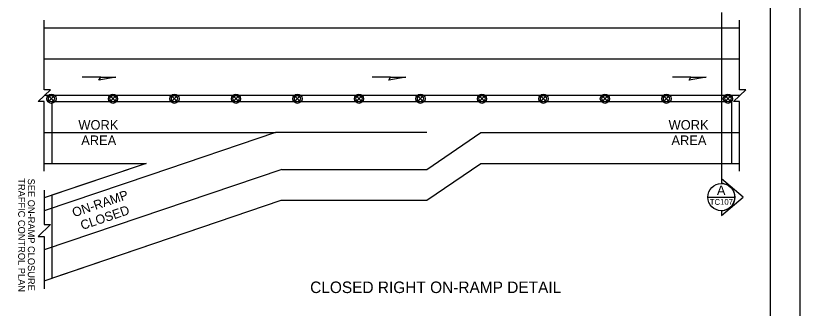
# Model space of a CAD drawing. Extents: x 99999 to 100116, y 99995 to 100013.
# Drawn here: x 100067.9 to 100076.06, y 100001.64 to 100004.69 of the extents above; entities that cross this region are included whole.
import ezdxf

# ---------------------------------------------------------------- set-up
doc = ezdxf.new("R2010")
doc.units = 0
for name, color, linetype in [('RD_MK_LineEdgeYellow', 7, 'Continuous'), ('RD_MK_LineLane', 7, 'Continuous'), ('SH_DE_DetailHeading2Text', 7, 'Continuous'), ('SH_GI_PlotLimits', 7, 'Continuous'), ('SH_GI_SheetBorder', 7, 'Continuous'), ('SH_TI_WZSectionCut', 7, 'Continuous'), ('TR_WZ_TrafficSafetyDrum', 7, 'Continuous'), ('TR_WZ_WorkAreaLabel', 7, 'Continuous'), ('TR_WZ_WorkZoneDetails', 7, 'Continuous')]:
    doc.layers.add(name, color=color, linetype=linetype)

msp = doc.modelspace()

# ---------------------------------------------------------------- linework, layer by layer
at = {"layer": 'RD_MK_LineEdgeYellow'}
for p, q in [((100068.195, 100004.238), (100075.43, 100004.238)), ((100068.195, 100003.47), (100069.2533, 100003.47)), ((100072.1758, 100003.086), (100072.7368, 100003.47)), ((100072.7368, 100003.47), (100075.43, 100003.47)), ((100070.6655, 100003.086), (100068.195, 100002.2517)), ((100070.6655, 100003.086), (100072.1758, 100003.086)), ((100069.2943, 100003.0282), (100068.195, 100002.657))]:
    msp.add_line(p, q, dxfattribs=at)
at = {"layer": 'RD_MK_LineLane'}
for points in [[(100075.43, 100003.854), (100068.195, 100003.854)], [(100072.1758, 100003.47), (100070.6024, 100003.47)]]:
    msp.add_lwpolyline(points, dxfattribs=at)
at = {"layer": 'SH_GI_PlotLimits'}
msp.add_lwpolyline([(100059.0625, 99999.6875), (100076.0625, 99999.6875), (100076.0625, 100010.6875), (100059.0625, 100010.6875)], close=True, dxfattribs=at)
at = {"layer": 'SH_GI_SheetBorder'}
msp.add_line((100075.75, 100010.375), (100075.75, 100000), dxfattribs=at)
at = {"layer": 'SH_TI_WZSectionCut'}
for p, q in [((100075.2407, 100004.718), (100075.2407, 100002.99)), ((100075.2407, 100002.99), (100075.2407, 100002.94)), ((100075.4689, 100002.7988), (100075.2407, 100002.99)), ((100075.2407, 100002.6077), (100075.4689, 100002.7988)), ((100075.2407, 100002.6576), (100075.2407, 100002.6077))]:
    msp.add_line(p, q, dxfattribs=at)
msp.add_lwpolyline([(100075.0995, 100002.7988), (100075.3819, 100002.7988)], dxfattribs=at)
msp.add_circle((100075.2407, 100002.7988), 0.1412, dxfattribs=at)
msp.add_arc((100075.2407, 100002.7988), 0.1412, 269.99779, 90.00221, dxfattribs=at)
at = {"layer": 'TR_WZ_TrafficSafetyDrum'}
for p, q in [((100068.2468, 100003.8446), (100068.292, 100003.7993)), ((100068.292, 100003.8446), (100068.2468, 100003.7993)), ((100068.8868, 100003.8446), (100068.932, 100003.7993)), ((100068.932, 100003.8446), (100068.8868, 100003.7993)), ((100069.5268, 100003.8446), (100069.572, 100003.7993)), ((100069.572, 100003.8446), (100069.5268, 100003.7993)), ((100070.1668, 100003.8446), (100070.212, 100003.7993)), ((100070.212, 100003.8446), (100070.1668, 100003.7993)), ((100070.8068, 100003.8446), (100070.852, 100003.7993)), ((100070.852, 100003.8446), (100070.8068, 100003.7993)), ((100071.4468, 100003.8446), (100071.492, 100003.7993)), ((100071.492, 100003.8446), (100071.4468, 100003.7993)), ((100072.0868, 100003.8446), (100072.132, 100003.7993)), ((100072.132, 100003.8446), (100072.0868, 100003.7993)), ((100072.7268, 100003.8446), (100072.772, 100003.7993)), ((100072.772, 100003.8446), (100072.7268, 100003.7993)), ((100073.3668, 100003.8446), (100073.412, 100003.7993)), ((100073.412, 100003.8446), (100073.3668, 100003.7993)), ((100074.0068, 100003.8446), (100074.052, 100003.7993)), ((100074.052, 100003.8446), (100074.0068, 100003.7993)), ((100074.6468, 100003.8446), (100074.692, 100003.7993)), ((100074.692, 100003.8446), (100074.6468, 100003.7993)), ((100075.2868, 100003.8446), (100075.332, 100003.7993)), ((100075.332, 100003.8446), (100075.2868, 100003.7993))]:
    msp.add_line(p, q, dxfattribs=at)
for centre, radius in [((100068.2694, 100003.822), 0.048), ((100068.2694, 100003.822), 0.048), ((100068.2694, 100003.822), 0.032), ((100068.9094, 100003.822), 0.048), ((100068.9094, 100003.822), 0.048), ((100068.9094, 100003.822), 0.032), ((100069.5494, 100003.822), 0.048), ((100069.5494, 100003.822), 0.048), ((100069.5494, 100003.822), 0.032), ((100070.1894, 100003.822), 0.048), ((100070.1894, 100003.822), 0.048), ((100070.1894, 100003.822), 0.032), ((100070.8294, 100003.822), 0.048), ((100070.8294, 100003.822), 0.048), ((100070.8294, 100003.822), 0.032), ((100071.4694, 100003.822), 0.048), ((100071.4694, 100003.822), 0.048), ((100071.4694, 100003.822), 0.032), ((100072.1094, 100003.822), 0.048), ((100072.1094, 100003.822), 0.048), ((100072.1094, 100003.822), 0.032), ((100072.7494, 100003.822), 0.048), ((100072.7494, 100003.822), 0.048), ((100072.7494, 100003.822), 0.032), ((100073.3894, 100003.822), 0.048), ((100073.3894, 100003.822), 0.048), ((100073.3894, 100003.822), 0.032), ((100074.0294, 100003.822), 0.048), ((100074.0294, 100003.822), 0.048), ((100074.0294, 100003.822), 0.032), ((100074.6694, 100003.822), 0.048), ((100074.6694, 100003.822), 0.048), ((100074.6694, 100003.822), 0.032), ((100075.3094, 100003.822), 0.048), ((100075.3094, 100003.822), 0.048), ((100075.3094, 100003.822), 0.032)]:
    msp.add_circle(centre, radius, dxfattribs=at)
at = {"layer": 'TR_WZ_WorkZoneDetails'}
for p, q in [((100068.195, 100004.558), (100075.43, 100004.558)), ((100068.782, 100004.046), (100068.5891, 100004.046)), ((100071.7994, 100004.046), (100071.6065, 100004.046)), ((100074.9242, 100004.046), (100074.7313, 100004.046)), ((100069.2533, 100003.47), (100070.6024, 100003.47)), ((100070.6024, 100003.47), (100069.2943, 100003.0282)), ((100068.195, 100003.15), (100069.2533, 100003.15)), ((100069.2533, 100003.15), (100068.195, 100002.7929)), ((100072.1758, 100002.766), (100072.7368, 100003.15)), ((100072.7368, 100003.15), (100075.43, 100003.15)), ((100068.195, 100001.928), (100070.6601, 100002.766)), ((100070.6601, 100002.766), (100072.1758, 100002.766))]:
    msp.add_line(p, q, dxfattribs=at)
for points in [[(100068.195, 100003.07), (100068.195, 100003.792), (100068.131, 100003.792), (100068.259, 100003.9159), (100068.195, 100003.9159), (100068.195, 100004.638)], [(100075.43, 100003.07), (100075.43, 100003.792), (100075.366, 100003.792), (100075.494, 100003.9159), (100075.43, 100003.9159), (100075.43, 100004.638)], [(100068.195, 100002.8701), (100068.195, 100002.5136), (100068.259, 100002.5136), (100068.131, 100002.3897), (100068.195, 100002.3897), (100068.195, 100001.8453)]]:
    msp.add_lwpolyline(points, dxfattribs=at)
for points in [[(100068.9392, 100004.046), (100068.7641, 100004.0151), (100068.782, 100004.046)], [(100071.9566, 100004.046), (100071.7815, 100004.0151), (100071.7994, 100004.046)], [(100075.0815, 100004.046), (100074.9064, 100004.0151), (100074.9242, 100004.046)], [(100068.275, 100003.79), (100068.275, 100003.15), (100069.2533, 100003.15), (100068.275, 100002.8199), (100068.275, 100002.8199), (100068.275, 100002.8199), (100068.275, 100001.9552), (100068.275, 100001.9552), (100068.275, 100001.9552), (100069.3341, 100002.3152), (100070.6601, 100002.766), (100072.1758, 100002.766), (100072.7368, 100003.15), (100075.35, 100003.15), (100075.35, 100003.79)]]:
    msp.add_lwpolyline(points, close=True, dxfattribs=at)

# ---------------------------------------------------------------- texts
at = {"layer": 'SH_DE_DetailHeading2Text'}
msp.add_text('CLOSED RIGHT ON-RAMP DETAIL', height=0.12, rotation=360, dxfattribs=at).set_placement((100070.9618, 100001.8009))
at = {"layer": 'SH_TI_WZSectionCut'}
for s, height, rotation, p in [('A', 0.1, 0.00995, (100075.1945, 100002.8195)), ('TC107', 0.06, 360, (100075.1209, 100002.7188))]:
    msp.add_text(s, height=height, rotation=rotation, dxfattribs=at).set_placement(p)
at = {"layer": 'TR_WZ_WorkAreaLabel'}
for s, p in [('WORK', (100068.5496, 100003.5)), ('WORK', (100074.6919, 100003.5)), ('AREA', (100068.5793, 100003.34)), ('AREA', (100074.7215, 100003.34))]:
    msp.add_text(s, height=0.1, dxfattribs=at).set_placement(p)
at = {"layer": 'TR_WZ_WorkZoneDetails'}
for s, height, rotation, p in [('TRAFFIC CONTROL PLAN', 0.072, 270, (100067.923, 100002.9948)), ('SEE ON-RAMP CLOSURE', 0.072, 270, (100068.0238, 100002.9908)), ('ON-RAMP', 0.096, 18.65903, (100068.5039, 100002.589)), ('ON-RAMP', 0.096, 18.65903, (100068.5039, 100002.589)), ('CLOSED', 0.096, 18.65903, (100068.5907, 100002.4562)), ('CLOSED', 0.096, 18.65903, (100068.5907, 100002.4562))]:
    msp.add_text(s, height=height, rotation=rotation, dxfattribs=at).set_placement(p)

doc.saveas('drawing.dxf')
